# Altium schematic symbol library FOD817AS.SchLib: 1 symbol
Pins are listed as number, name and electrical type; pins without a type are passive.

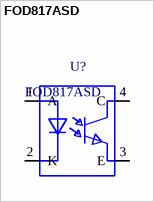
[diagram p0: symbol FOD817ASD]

## FOD817ASD
designator U?
IC, Optocoupler, 5000V, 80-160% CTR; Manufacturer: Fairchild Optoelectronics Group; Value: FODA817ASD; Area: 93500; PCB DECAL: SMT_4PDIP
footprint FOD817AS (FOD817AS recommended footprint)
pins: 1 A, 2 K, 3 E, 4 C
